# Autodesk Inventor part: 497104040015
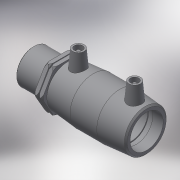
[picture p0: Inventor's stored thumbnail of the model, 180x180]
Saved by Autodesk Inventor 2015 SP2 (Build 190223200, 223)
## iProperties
Created: 2017-06
Part Number: 497104040015
Material: Generic
Description: PLASSON PE MALE TRANSITION COUPLER 40-1.1/2"
Document SubType Name: Modeling
Designer: KIM
Mass: 55.0731 g
Surface Area: 148.067 cm^2
Volume: 55.0731 cm^3
Density: 1 g/cm^3
Appearance: Default
Author: KIM
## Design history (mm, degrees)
derived "497104.ipt"
feature "Solid1::497104.ipt"
tag "TaggingFeature1"
body "Solid1"
other parameters: "d0" = 97, "d2" = 56, "d3" = 47, "d4" = 32.33333, "d5" = 50.4, "d6" = 38, "d8" = 168 deg, "d10" = 18.8, "d11" = 6.26667, "d29" = 46, "d30" = 14, "d31" = 33.95, "d34" = 5 deg, "d41" = 4, "d42" = 14, "d43" = 0, "d48" = 3, "d49" = 0, "d58" = 47.803, "d59" = 38.2424, "d60" = 36, "d61" = 66.9242, "d62" = 0.95606, "d65" = 1.68, "d70" = 0.1, "d73" = 18.8, "d75" = 0, "d76" = 1, "d77" = 4.5, "d78" = 66.9242, "L_" = 137, "L_2" = 47, "D_1" = 56, "A_" = 46, "d_2" = 12, "R_" = 47.803
